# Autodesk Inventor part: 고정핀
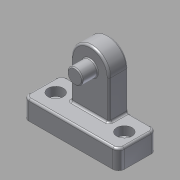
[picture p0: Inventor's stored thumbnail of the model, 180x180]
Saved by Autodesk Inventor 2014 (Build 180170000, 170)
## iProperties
Created: 2017-07
Part Number: 고정핀
Material: 알루미늄 6061
Document SubType Name: Modeling
Designer: mduedu
Density: 2.71 g/cm^3
Appearance: 알루미늄 - 평지
Mass: 41.2292 g
Surface Area: 53.4313 cm^2
Volume: 15.2137 cm^3
Author: mduedu
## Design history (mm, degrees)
sketch "스케치1"
  geometry: L1 (-25, 0)-(25, 0); L2 (-25, 10)-(25, 10); L3 (-25, 0)-(-25, 10); L4 (25, 0)-(25, 10); L5 (-10, 10)-(10, 10); L6 (10, 10)-(10, 40); L7 (10, 40)-(-10, 40); L8 (-10, 40)-(-10, 10); 3 further points
  constraints: 16 end point, 4 parallel, 2 horizontal, 2 midpoint, 2 perpendicular, 1 coincident, 1 point on line, 1 vertical alignment
  dimensions: "d0" = 50 distance of L1.start L1.end; "d2" = 10 distance of L1.end L2.end; "d3" = 20 distance of L6.end L7.end; "d4" = 40 distance between parallel lines of L7 L1
extrude "돌출1" new body sketch "스케치1" stored distance "d5" = 20; taper "d6" = 0 deg
extrude "돌출2" join sketch "스케치1" distance "d7" = 10; taper "d8" = 0 deg
fillet "모깎기1"
sketch "스케치2"
  geometry: C1 r 4 at (0, 30); A1 r 10 centre (0, 30) between (10, 30) and (-10, 30) reference; 1 further point
  constraints: 1 centre point, 1 coincident
  dimensions: "d9" = 8 diameter of C1
extrude "돌출3" join sketch "스케치2" distance "d10" = 8; taper "d11" = 0 deg
fillet "모깎기2" dims "d12" = 0.5
fillet "모깎기3" dims "d13" = 1
fillet "모깎기4" dims "d14" = 1
fillet "모깎기5" dims "d15" = 3
fillet "모깎기6" dims "d16" = 1
chamfer "모따기1" distance "d18" = 0.5; stored, may be unused: second distance "d19" = 2, angle "d20" = 45 deg
sketch "스케치3"
  geometry: L1 (-16, 8)-(-16, -6) reference; L2 (34, -6)-(34, 8) reference; L3 (-16, 1)-(34, 1); L4 (-13, -9)-(31, -9) reference; L5 (9, 1)-(9, -9); 2 further points
  constraints: 4 end point, 3 midpoint, 1 point on line, 1 symmetric about line
  dimensions: "d21" = 7 distance from line of point (-9, 1) L1
sketch "스케치4"
  geometry: L1 (-16, 1)-(34, 1) reference; L2 (9, 1)-(9, -9) reference; 7 further points
  constraints: 2 coincident
hole "구멍1" sketch "스케치4" at (27, 1), (-9, 1) diameter "d22" = 4.5; stored, may be unused: countersink angle "d26" = 90 deg, drill point angle "d28" = 0 deg; dims "d23" = 6, "d24" = 8, "d25" = 4.6, "d27" = 8
node "솔리드1"
